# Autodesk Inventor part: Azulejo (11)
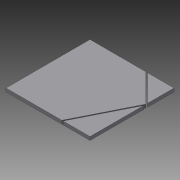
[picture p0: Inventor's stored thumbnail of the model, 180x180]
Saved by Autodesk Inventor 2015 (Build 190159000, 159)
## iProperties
Created: 2015-04
Part Number: Azulejo (11)
Material: Genérico
Document SubType Name: Modeling
Designer: Felipe
Density: 1 g/cm^3
Appearance: Padrão
Author: Felipe
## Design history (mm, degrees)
sketch "Sketch2"
  geometry: L1 (-1510, -7490)-(-1510, -6010); L2 (992.445, 7510)-(992.445, 8990); L3 (1012.445, 7510)-(1012.445, 8990); L4 (-3010, 4510)-(-3010, 5990); L5 (-3010, 3010)-(-3010, 4490); L6 (-3010, -1490)-(-3010, -10); L7 (-1510, 7490)-(-2990, 7490); L8 (-2990, 5990)-(-2990, 4510); L9 (-2990, 4490)-(-2990, 3010); L10 (-1510, 2990)-(-2990, 2990); L11 (-2990, 10)-(-1510, 10); L12 (-1510, -10)-(-2990, -10); L13 (-1510, -1490)-(-1510, -10); L14 (-3010, 7490)-(-4490, 7490); L15 (-3010, 5990)-(-4490, 5990); L16 (-10, 9010)-(-10, 10490); L17 (-10, 7510)-(-10, 8990); L18 (-10, 7490)-(-1490, 7490); L19 (-1490, 6010)-(-10, 6010); L20 (-10, 5990)-(-1490, 5990); L21 (-1490, 5990)-(-1490, 4510); L22 (-1490, 4490)-(-1490, 3010); L23 (-1490, -10)-(-1490, -1490); L24 (-1490, -1490)-(-10, -1490); L25 (-10, -1510)-(-1490, -1510); L26 (-10, -2990)-(-10, -1510); L27 (-10, -5990)-(-10, -4510); L28 (-1490, -7490)-(-10, -7490); L29 (10, 8990)-(10, 7510); L30 (1490, 7510)-(1490, 8990); L31 (10, 6010)-(1490, 6010); L32 (1490, 6010)-(1490, 7490); L33 (1490, 5990)-(10, 5990); L34 (4490, -6010)-(3010, -6010); L35 (10, -1510)-(10, -2990); L36 (10, -3010)-(10, -4490); L37 (10, -4510)-(10, -5990); L38 (10, -5990)-(1490, -5990); L39 (1490, -6010)-(10, -6010); L40 (10, -7490)-(1490, -7490); L41 (2990, 9010)-(2990, 10490); L42 (1510, 8990)-(1510, 7510); L43 (1510, 7510)-(2990, 7510); L44 (2990, 7490)-(1510, 7490); L45 (1510, 7490)-(1510, 6010); L46 (1510, -5990)-(2990, -5990); L47 (2990, -6010)-(1510, -6010); L48 (1510, -7490)-(2990, -7490); L49 (3010, 10490)-(3010, 9010); L50 (3010, 9010)-(4490, 9010); L51 (4490, 8990)-(3010, 8990); L52 (4490, 7490)-(3010, 7490); L53 (4490, 1510)-(4490, 2990); L54 (4490, 10)-(4490, 1490); L55 (4490, -1490)-(4490, -10); L56 (4490, -2990)-(4490, -1510); L57 (3010, -5990)-(4490, -5990); L58 (3010, -7490)-(4490, -7490); L59 (4510, 9010)-(5990, 9010); L60 (5990, 8990)-(4510, 8990); L61 (4510, 7510)-(5990, 7510); L62 (5990, 7490)-(4510, 7490); L63 (4510, 3010)-(5990, 3010); L64 (5990, 2990)-(4510, 2990)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; A1 r 250 centre (6000, 2010) between (5990, 2259.8) and (5990, 1760.2); A2 r 250 centre (6000, 2010) between (6010, 1760.2) and (6010, 2259.8); A3 r 270 centre (6000, 2010) between (5990, 2279.815) and (5990, 1740.185); A4 r 270 centre (6000, 2010) between (6010, 1740.185) and (6010, 2279.815); A5 r 3010.017 centre (0, 0) between (-1490, -2615.358) and (-346.554, -2990); A6 r 2990.017 centre (0, 0) between (-1490, -2592.316) and (-10, -2990); A7 r 3010.017 centre (0, 0) between (-2603.863, -1510) and (-1510, -2603.863); A8 r 2990.017 centre (0, 0) between (-2580.717, -1510) and (-1510, -2580.717); A9 r 3010.017 centre (0, 0) between (-2990, -346.554) and (-2615.358, -1490); A10 r 2990.017 centre (0, 0) between (-2990, -10) and (-2592.316, -1490); A11 r 2131.367 centre (7500, -1500) between (7490, 631.344) and (6010, 24.017); A12 r 2131.367 centre (7500, -1500) between (5975.983, -10) and (5368.656, -1490); A13 r 2131.367 centre (7500, -1500) between (5368.656, -1510) and (5975.983, -2990); A14 r 2131.367 centre (7500, -1500) between (6010, -3024.017) and (7190, -3608.703); A15 r 1831.367 centre (7500, -1500) between (7490.321, 331.342) and (6463.753, 10); A16 r 1831.367 centre (7500, -1500) between (6435.196, -10) and (6010, -435.196); A17 r 1831.367 centre (7500, -1500) between (5990, -463.753) and (5668.66, -1490); A18 r 1831.367 centre (7500, -1500) between (5668.66, -1510) and (5990, -2536.247); A19 r 1831.367 centre (7500, -1500) between (6010, -2564.804) and (6435.196, -2990); A20 r 1831.367 centre (7500, -1500) between (6463.753, -3010) and (7490, -3331.34); A21 r 2111.367 centre (7500, -1500) between (7490.047, 611.344) and (6024.272, 10); A22 r 2111.367 centre (7500, -1500) between (5990, -24.272) and (5388.656, -1490); A23 r 2111.367 centre (7500, -1500) between (5388.656, -1510) and (5990, -2975.728); A24 r 2111.367 centre (7500, -1500) between (6024.272, -3010) and (7210, -3591.357); A25 r 1811.367 centre (7500, -1500) between (7490.374, 311.342) and (6499.524, 10); A26 r 1811.367 centre (7500, -1500) between (6469.975, -10) and (6010, -469.975); A27 r 1811.367 centre (7500, -1500) between (5990, -499.524) and (5688.66, -1490); A28 r 1811.367 centre (7500, -1500) between (5688.66, -1510) and (5990, -2500.476); A29 r 1811.367 centre (7500, -1500) between (6010, -2530.025) and (6469.975, -2990); A30 r 1811.367 centre (7500, -1500) between (6499.524, -3010) and (7490, -3311.34); A31 r 449.871 centre (7499.449, -4060.672) between (7510, -4510.419) and (7521.546, -4510); 2 further points
  constraints: 1114 end point, 64 point on circle, 31 centre point, 13 point on line, 1 other
extrude "Extrusion1" new body sketch "Sketch2" distance "d0" = 60; taper "d1" = 0 deg
sketch "Sketch3"
  geometry: L1 (-1510, 4024.142)-(-1510, 4490) reference; L2 (-1510, 4024.142)-(-1975.858, 4490) reference; L3 (-1510, 4490)-(-1975.858, 4490) reference; 1 further point
extrude "Extrusion2" new body sketch "Sketch3" distance "d2" = 60; taper "d3" = 0 deg
extrude "Extrusion3" new body sketch "Sketch2" distance "d4" = 60; taper "d5" = 0 deg
body "Solid1"
body "Solid2"
body "Solid3"
